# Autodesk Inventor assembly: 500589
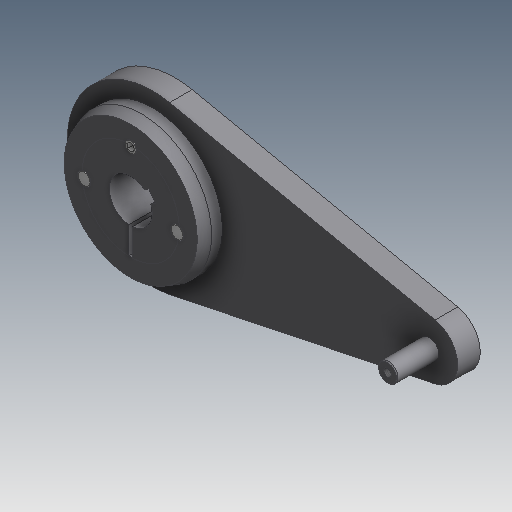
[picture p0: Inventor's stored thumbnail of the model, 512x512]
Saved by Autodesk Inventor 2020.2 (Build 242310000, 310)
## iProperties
Created: 2000-02
Part Number: 500589
Document SubType Name: Assembly
Designer: glanglot
Mass: 7177.99 g
Surface Area: 1497.9 cm^2
Volume: 916.634 cm^3
Density: 7.83081 g/cm^3
Control State: 0
Checked Out: False
Master: False
Shininess: 0.0
Length Units: 11269
Angle Units: 11279
Time Units: 11290
Mass Units: 11283
Length Display Precision: 3
Angle Display Precision: 2
Compacted: True
Dimensions: 150x62,5x345 mm
Mass: 7,178 kg
DocNumber: 500589.iam
Folder: 01 - Themengebiete\Simplification\01 - Packaging machine\Parts\
VDS_Category: 3D Komponenten
Density: 0.0
Volumn: 0.0
Area: 0.0
PropertySet Name: Model Information
Author: glanglot
Revision Number: -
Title: 500589
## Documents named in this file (7)
- D:\07 - DEMODATEN\OTX 2019 - Dataset - UPDATE - Dez2019\Designs\07-Packing machine\500589.iam
- D:\07 - DEMODATEN\OTX 2019 - Dataset - UPDATE - Dez2019\Designs\07-Packing machine\Parts\ADSK-011550.ipt
- D:\07 - DEMODATEN\OTX 2019 - Dataset - UPDATE - Dez2019\Designs\07-Packing machine\Parts\ADSK-011760.ipt
- D:\07 - DEMODATEN\OTX 2019 - Dataset - UPDATE - Dez2019\Designs\07-Packing machine\Parts\ADSK-011552.ipt
- D:\07 - DEMODATEN\OTX 2019 - Dataset - UPDATE - Dez2019\Designs\07-Packing machine\Parts\ADSK-011739.ipt
- D:\07 - DEMODATEN\OTX 2019 - Dataset - UPDATE - Dez2019\Content Center Files\de-DE\ISO 2338(2)\ISO 2338 - 12 h8 x 24.ipt
- D:\07 - DEMODATEN\OTX 2019 - Dataset - UPDATE - Dez2019\Content Center Files\de-DE\ISO 4026\ISO 4026 - M12 x 20 - ISO.ipt
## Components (7 placed, 6 different names)
1. ADSK-011550:1 — Insert:1, Flush:1, Fluchtend:5
2. ADSK-011760:1 — Insert:1, Flush:1, Passend:1, Passend:2, Passend:5, Fluchtend:2, Fluchtend:3, Fluchtend:4
3. ADSK-011552:1 — Fluchtend:5
4. ADSK-011739:1 — Passend:1, Passend:2, Passend:4
5. ISO 4026 M12 x 20:1 — Fluchtend:4
6. ISO 2338 12 h8 x 24:1 — Passend:5, Fluchtend:2
7. ISO 2338 12 h8 x 24:2 — Passend:4, Fluchtend:3
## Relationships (10: Flush 5, Mate 4, Insert 1)
- Insert:1: ADSK-011550:1 ↔ ADSK-011760:1
- Flush:1: ADSK-011550:1 ↔ ADSK-011760:1
- Passend:1 [Mate]: ADSK-011760:1 ↔ ADSK-011739:1
- Passend:2 [Mate]: ADSK-011760:1 ↔ ADSK-011739:1
- Passend:4 [Mate]: ADSK-011739:1 ↔ ISO 2338 12 h8 x 24:2
- Passend:5 [Mate]: ADSK-011760:1 ↔ ISO 2338 12 h8 x 24:1
- Fluchtend:2 [Flush]: ADSK-011760:1 ↔ ISO 2338 12 h8 x 24:1
- Fluchtend:3 [Flush]: ADSK-011760:1 ↔ ISO 2338 12 h8 x 24:2
- Fluchtend:4 [Flush]: ADSK-011760:1 ↔ ISO 4026 M12 x 20:1
- Fluchtend:5 [Flush]: ADSK-011550:1 ↔ ADSK-011552:1
